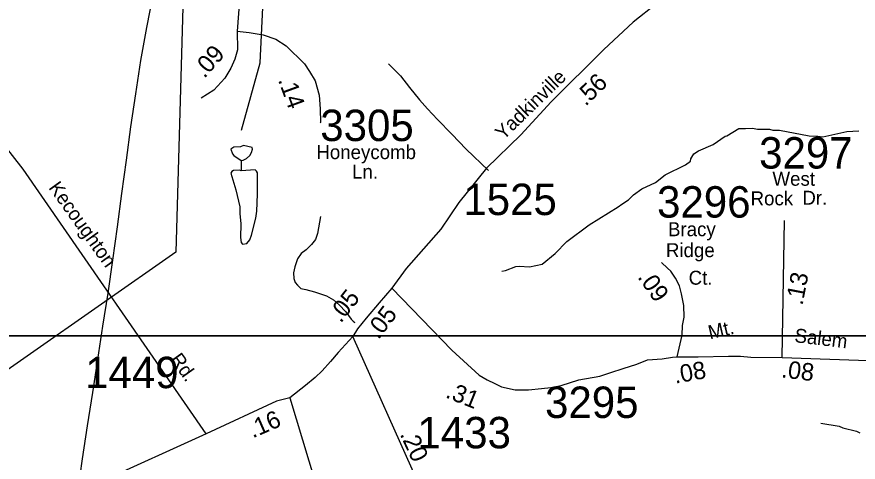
# Model space of a CAD drawing. Extents: x 1551653 to 1702041, y 811336 to 920032.
# Drawn here: x 1590899 to 1594852, y 874155 to 876248 of the extents above; entities that cross this region are included whole.
import ezdxf

# ---------------------------------------------------------------- set-up
doc = ezdxf.new("R2010")
doc.units = 0
for name, color, linetype in [('Old_Level_11', 7, 'Continuous'), ('Old_Level_17', 7, 'Continuous'), ('Old_Level_3', 7, 'Continuous'), ('Old_Level_32', 7, 'Continuous'), ('Old_Level_35', 7, 'Continuous'), ('Old_Level_56', 7, 'Continuous'), ('Old_Level_59', 7, 'Continuous'), ('Old_Level_62', 7, 'Continuous'), ('Old_Level_63', 7, 'Continuous'), ('Old_Level_8', 7, 'Continuous')]:
    doc.layers.add(name, color=color, linetype=linetype)

msp = doc.modelspace()

# ---------------------------------------------------------------- linework, layer by layer
at = {"layer": 'Old_Level_3'}
msp.add_lwpolyline([(1591185.666, 874014.417), (1591208.098, 874170.418), (1591231.447, 874326.344), (1591255.393, 874482.21), (1591279.612, 874638.032), (1591303.779, 874793.826), (1591327.572, 874949.606), (1591350.618, 875105.42), (1591372.312, 875261.594), (1591393.129, 875418.056), (1591413.787, 875574.614), (1591435.002, 875731.074), (1591457.493, 875887.242), (1591481.977, 876042.925), (1591509.172, 876197.929), (1591539.795, 876352.062)], dxfattribs=at)
at = {"layer": 'Old_Level_32'}
for p, q in [((1594494.672, 874647.909), (1594505.672, 875291.241)), ((1592963.968, 873658.595), (1592477.374, 874745.205)), ((1594494.672, 874647.909), (1594943.156, 874630.971)), ((1591788.81, 874288.264), (1591183.614, 874014.494))]:
    msp.add_line(p, q, dxfattribs=at)
for points in [[(1592466.769, 877359.31), (1592118.891, 877371.118), (1592068.038, 877355.699), (1592036.318, 877341.445), (1591998.306, 877305.665), (1591970.339, 877261.349), (1591959.54, 877231.57), (1591947.572, 877202.285), (1591943.245, 877174.026), (1591934.333, 877124.983), (1591940.04, 877021.111), (1591948.751, 876817.498), (1591953.206, 876787.775), (1591953.772, 876736.21), (1591958.227, 876681.224), (1591959.417, 876640.288), (1591960.902, 876582.329), (1591952.043, 876411.595), (1591934.806, 876180.608)], [(1594842.046, 876675.184), (1594628.094, 876594.546), (1594350.308, 876500.812), (1594131.252, 876426.144), (1593979.582, 876350.361), (1593906.563, 876310.644), (1593795.449, 876223.265), (1593657.349, 876094.58), (1593410.23, 875848.915), (1593267.368, 875693.222), (1593106.037, 875536.588), (1592975.874, 875376.13), (1592890.729, 875251.09), (1592727.766, 875066.22), (1592661.446, 874972.759)], [(1591788.81, 874288.264), (1590928.908, 875532.67), (1590759.371, 875746.559), (1590738.972, 875772.517), (1590706.667, 875888.14), (1590668.07, 876018.074), (1590528.311, 876487.095)], [(1591934.806, 876180.608), (1591936.178, 876093.554), (1591923.593, 876048.841), (1591904.69, 876006.469), (1591876.246, 875959.585), (1591824.378, 875904.329), (1591765.817, 875865.818)], [(1591934.806, 876180.608), (1591990.633, 876174.382), (1592057.197, 876164.291), (1592115.508, 876143.771), (1592164.03, 876111.956), (1592251.034, 876028.236), (1592273.62, 875991.902), (1592300.933, 875948.094), (1592320.083, 875879.809), (1592324.654, 875815.585), (1592326.327, 875751.957), (1592324.976, 875747.955)], [(1594001.929, 874651.015), (1594024.781, 874752.642), (1594027.32, 874798.373), (1594034.937, 874836.482), (1594032.398, 874892.376), (1594022.242, 874945.73), (1594012.086, 874983.839), (1593994.313, 875019.409), (1593971.461, 875052.438), (1593956.226, 875067.681), (1593928.296, 875093.087)], [(1592661.446, 874972.759), (1592601.893, 874903.701), (1592540.086, 874832.169), (1592500.402, 874781.331), (1592477.374, 874745.205)], [(1592661.446, 874972.759), (1592942.968, 874681.543), (1593070.693, 874564.756), (1593108.779, 874541.89), (1593144.635, 874525.777), (1593176.727, 874508.74), (1593240.204, 874496.036), (1593303.681, 874496.036), (1593364.619, 874501.117), (1593407.783, 874506.198), (1593456.026, 874516.362), (1593539.816, 874541.768), (1593638.84, 874559.552), (1593689.622, 874577.337), (1593748.021, 874595.121), (1593811.498, 874615.446), (1593862.279, 874635.772), (1593930.835, 874640.853), (1593979.078, 874648.475), (1594001.929, 874651.015)], [(1592477.374, 874745.205), (1592409.4, 874670.155), (1592372.891, 874628.848), (1592333.783, 874584.166), (1592300.6, 874552.907), (1592255.405, 874516.316), (1592181.639, 874458.174), (1592118.387, 874441.517), (1591788.81, 874288.264)], [(1594001.929, 874651.015), (1594100.954, 874651.015), (1594243.142, 874653.556), (1594299.003, 874653.556), (1594347.245, 874648.475), (1594494.672, 874647.909)]]:
    msp.add_lwpolyline(points, dxfattribs=at)
at = {"layer": 'Old_Level_35'}
msp.add_line((1592181.639, 874458.174), (1592313.711, 874022.969), dxfattribs=at)
for points in [[(1592645.716, 876027.848), (1592701.015, 875971.149), (1592744.115, 875916.447), (1592791.316, 875857.849), (1592828.714, 875815.25), (1592875.916, 875766.448), (1592943.015, 875697.449), (1593010.013, 875626.448), (1593114.613, 875526.849)], [(1592325.116, 875310.149), (1592311.914, 875230.35), (1592301.616, 875202.551), (1592283.315, 875178.65), (1592258.716, 875153.152), (1592234.615, 875135.452), (1592218.315, 875111.551), (1592205.717, 875073.851), (1592199.316, 875045.951), (1592200.815, 875017.85), (1592206.616, 874999.75), (1592218.315, 874987.45), (1592234.218, 874971.351), (1592256.216, 874967.151), (1592298.017, 874956.449), (1592353.817, 874937.552), (1592387.515, 874919.051), (1592413.217, 874894.652), (1592444.716, 874862.25), (1592470.316, 874827.851), (1592487.336, 874810.465), (1592479.4, 874816.82)]]:
    msp.add_lwpolyline(points, dxfattribs=at)
at = {"layer": 'Old_Level_56'}
msp.add_lwpolyline([(1594795.417, 882224.158), (1594492.304, 881911.724), (1594314.227, 881725.829), (1594181.696, 881585.23), (1591756.719, 879036.343), (1591646.319, 875141.951), (1590597.318, 874408.75), (1590660.92, 873411.252), (1590633.821, 873059.655), (1590510.018, 871286.457), (1590671.819, 869193.062), (1591400.592, 867299.426), (1591680.416, 866598.966), (1590226.62, 861827.778), (1590099.721, 859136.383), (1590298.021, 857488.686)], dxfattribs=at)
at = {"layer": 'Old_Level_59'}
msp.add_lwpolyline([(1591954.555, 875715.728), (1592042.625, 876032.431), (1592054.621, 876291.514), (1592116.546, 876565.976), (1592168.63, 876663.376), (1592303.554, 876769.08), (1592462.572, 876824.957), (1593436.569, 876752.574), (1593787.618, 876765.184), (1594118.06, 876837.26)], dxfattribs=at)
at = {"layer": 'Old_Level_62'}
msp.add_line((1591952.915, 875573.114), (1591953.12, 875524.927), dxfattribs=at)
for points in [[(1594101.451, 875618.431), (1594170.348, 875648.983), (1594226.942, 875687.123), (1594234.939, 875688.968), (1594291.431, 875722.802), (1594323.419, 875723.93), (1594355.408, 875725.365), (1594379.296, 875720.957), (1594435.275, 875720.034), (1594451.269, 875715.83), (1594483.155, 875715.215), (1594622.693, 875688.866), (1594662.678, 875688.251), (1594686.567, 875683.842), (1594798.935, 875709.884), (1594855.017, 875712.96)], [(1591963.373, 875642.934), (1591950.557, 875637.5), (1591918.466, 875635.962), (1591904.42, 875626.12), (1591912.109, 875604.077), (1591918.056, 875595.977), (1591952.915, 875573.114)], [(1591952.915, 875573.114), (1591961.732, 875575.37), (1591977.829, 875583.162), (1591994.028, 875597.003), (1592002.23, 875610.844), (1592006.433, 875626.838), (1592004.485, 875634.835), (1591963.373, 875642.934)], [(1593178.306, 875052.384), (1593195.53, 875055.563), (1593243.718, 875074.94), (1593259.814, 875076.683), (1593307.796, 875074.12), (1593367.877, 875085.295), (1593428.06, 875135.533), (1593483.834, 875192.23), (1593588.103, 875270.457), (1593725.18, 875354.734), (1593741.379, 875368.472), (1593773.572, 875388.055), (1593795.82, 875411.841), (1593836.216, 875439.318), (1593900.602, 875470.485), (1593944.996, 875505.857), (1594041.575, 875552.609), (1594063.824, 875570.346), (1594065.874, 875580.291), (1594080.228, 875604.179), (1594101.451, 875618.431)], [(1591953.12, 875524.927), (1591945.225, 875527.592), (1591917.133, 875525.952), (1591909.136, 875522.056), (1591905.035, 875514.162), (1591928.104, 875435.832), (1591947.071, 875355.554), (1591946.763, 875323.566), (1591952.197, 875275.481), (1591949.326, 875211.505), (1591953.12, 875187.514), (1591958.964, 875179.414), (1591979.059, 875183.207), (1591993.208, 875200.944), (1592001.512, 875222.885), (1592022.53, 875302.65), (1592026.836, 875334.536), (1592029.809, 875414.506), (1592029.092, 875514.572), (1592025.093, 875522.569), (1592019.249, 875528.618), (1591953.12, 875524.927)], [(1594677.032, 874338.085), (1594762.846, 874324.654), (1594780.686, 874316.35), (1594844.457, 874301.278), (1594860.246, 874292.974)]]:
    msp.add_lwpolyline(points, dxfattribs=at)
at = {"layer": 'Old_Level_63'}
for points in [[(1571207.969, 918191.523), (1633724.041, 918191.523), (1633724.041, 874749.337), (1571207.969, 874749.337), (1571207.969, 918191.523)], [(1569096.749, 874749.337), (1631612.821, 874749.337), (1631612.821, 831307.151), (1569096.749, 831307.151), (1569096.749, 874749.337)]]:
    msp.add_lwpolyline(points, dxfattribs=at)

# ---------------------------------------------------------------- texts
at = {"layer": 'Old_Level_11'}
for s, height, rotation, p in [('Yadkinville', 65.61666, 44.258647, (1593185.001, 875666.654)), ('Kecoughton', 65.6167, 305.663294, (1591045.493, 875444.828)), ('Mt.', 65.6167, 13.009853, (1594155.64, 874732.097)), ('Salem', 65.6167, 353.174867, (1594550.593, 874719.593)), ('Rd.', 65.6167, 305.663294, (1591616.579, 874638.572))]:
    msp.add_text(s, height=height, rotation=rotation, dxfattribs=at).set_placement(p)
for s, p in [('Honeycomb', (1592306.421, 875579.708)), ('Ln.', (1592474.146, 875487.661)), ('West', (1594449.426, 875454.518)), ('Rock', (1594346.555, 875362.328)), ('Dr.', (1594589.948, 875365.267)), ('Bracy', (1593958.536, 875217.323)), ('Ridge', (1593948.931, 875118.816)), ('Ct.', (1594055.71, 874989.399))]:
    msp.add_text(s, height=65.6167, dxfattribs=at).set_placement(p)
at = {"layer": 'Old_Level_17'}
for s, rotation, p in [('.09', 48.797111, (1591780.309, 875955.666)), ('.56', 44.831014, (1593571.681, 875824.703)), ('.14', 290.100106, (1592125.598, 875951.775)), ('.09', 305.152433, (1593813.281, 875024.839)), ('.13', 78.955353, (1594590.275, 874889.387)), ('.05', 52.024486, (1592421.022, 874805.817)), ('.05', 52.857011, (1592598.084, 874728.152)), ('.08', 353.174867, (1594488.554, 874553.941)), ('.08', 10.294439, (1593992.609, 874523.872)), ('.31', 338.141453, (1592908.858, 874460.879)), ('.16', 23.593528, (1592007.622, 874266.517)), ('.20', 294.772919, (1592697.541, 874286.988))]:
    msp.add_text(s, height=82.0208, rotation=rotation, dxfattribs=at).set_placement(p)
at = {"layer": 'Old_Level_8'}
for s, p in [('3305', (1592324.774, 875664.499)), ('3297', (1594386.813, 875535.266)), ('1525', (1592996.947, 875316.658)), ('3296', (1593907.265, 875304.792)), ('1449', (1591220.066, 874503.133)), ('3295', (1593380.982, 874363.011)), ('1433', (1592781.331, 874220.327))]:
    msp.add_text(s, height=147.6375, dxfattribs=at).set_placement(p)

doc.saveas('drawing.dxf')
